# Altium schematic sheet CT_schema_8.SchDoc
size 374 x 245 mm
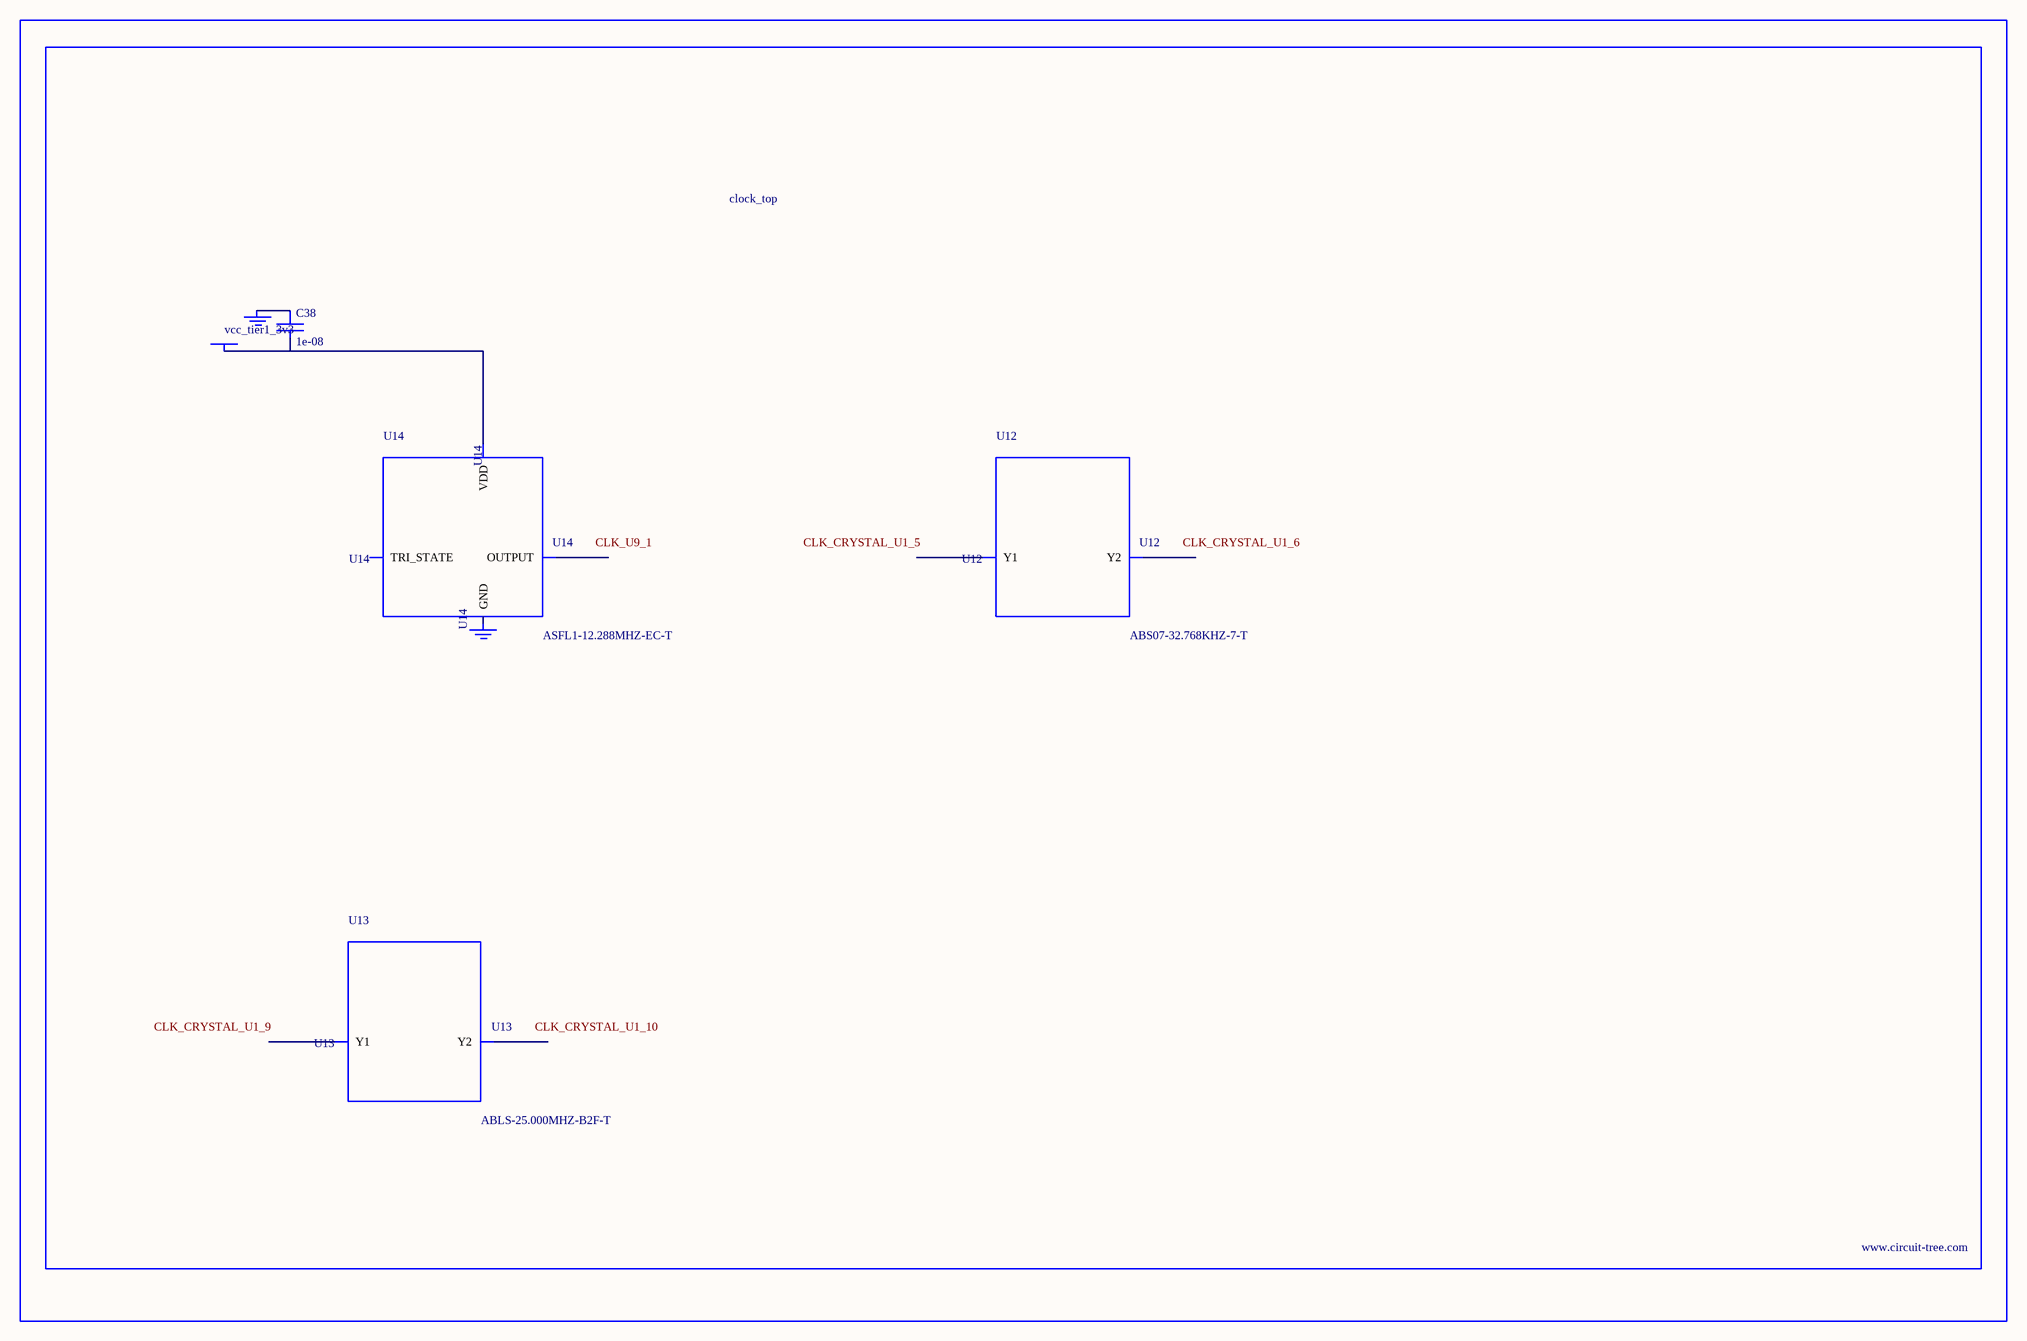
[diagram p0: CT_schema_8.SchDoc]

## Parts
BORDER7  (no value)
C38  1e-08  [C0402]
GND_INSTANCE_7_0  (no value)
GND_INSTANCE_7_1  (no value)
POWER_INSTANCE_7_0  vcc_tier1_3v3
U12  ABS07-32.768KHZ-7-T  [ABS07-32.768KHZ-7-T]
U13  ABLS-25.000MHZ-B2F-T  [ABLS-25.000MHZ-B2F-T]
U14  ASFL1-12.288MHZ-EC-T  [ASFL1]

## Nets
NetC38_1: C38.1 GND_INSTANCE_7_0.0(GND)
NetC38_2: C38.2 POWER_INSTANCE_7_0.0(PWR) U14.4(VDD)

Not connected (* = marked no-connect by the designer): GND_INSTANCE_7_1 0(GND); U12 1(Y1) 2(Y2); U13 1(Y1) 2(Y2); U14 1(TRI_STATE) 2(GND) 3(OUTPUT)

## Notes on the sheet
- Labels drawn without touching a wire or pin: CLK_CRYSTAL_U1_5, CLK_CRYSTAL_U1_6, CLK_CRYSTAL_U1_9, CLK_CRYSTAL_U1_10, CLK_U9_1

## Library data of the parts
BORDER7 = BORDER_PAGE7
C38 = C0402C103K3RAC
GND_INSTANCE_7_0 GND_INSTANCE_7_1 = GND
POWER_INSTANCE_7_0 = PWR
